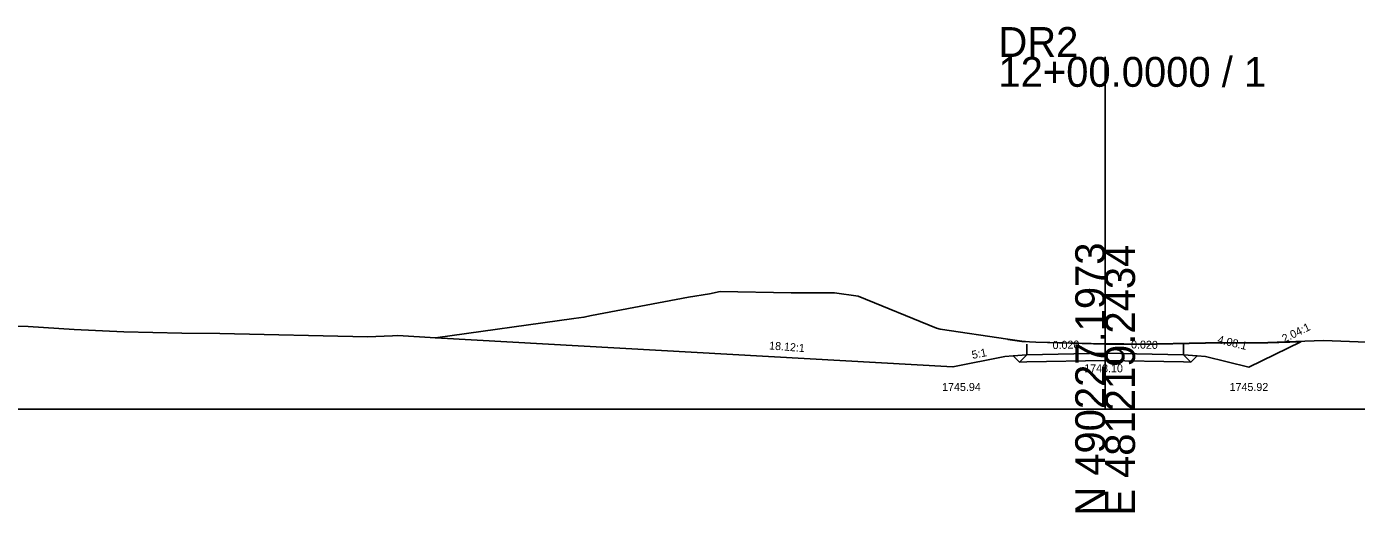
# Model space of a CAD drawing. Extents: x -26 to 403, y -10 to 2576.
# Drawn here: x 98.9 to 223.5, y 1990.3 to 2035.8 of the extents above; entities that cross this region are included whole.
import ezdxf

# ---------------------------------------------------------------- set-up
doc = ezdxf.new("R2010")
doc.units = 0
for name, color, linetype in [('Exist Cross Section Cell', 7, 'Continuous'), ('Exist XS Center Line Elevation Label', 7, 'Continuous'), ('Exist XS Ground Line', 7, 'Continuous'), ('Prop Road Sect_ Boring - Header (ID Tx)', 7, 'Continuous'), ('Prop XS Ditch Slope Text', 7, 'Continuous'), ('Prop XS Ditch Standard Text', 7, 'Continuous'), ('Prop XS Dump Level', 7, 'Continuous'), ('Prop XS Earthwork Shape', 7, 'Continuous'), ('Prop XS EOT Tick Mark', 7, 'Continuous'), ('Prop XS Finish Grade', 7, 'Continuous'), ('Prop XS Finish Grade Earthwork', 7, 'Continuous'), ('Prop XS Finish Grade Pavement', 7, 'Continuous'), ('Prop XS Pvmt Edge Slope', 7, 'Continuous'), ('Prop XS SE Text', 7, 'Continuous'), ('Prop XS Side Slope Text', 7, 'Continuous'), ('Prop XS Subgrade Earthwork', 7, 'Continuous')]:
    doc.layers.add(name, color=color, linetype=linetype)

msp = doc.modelspace()

# ---------------------------------------------------------------- linework, layer by layer
at = {"layer": 'Exist Cross Section Cell'}
for p, q in [((200, 2000), (200, 2033)), ((0, 2000), (200, 2000)), ((200, 2000), (400, 2000))]:
    msp.add_line(p, q, dxfattribs=at)
at = {"layer": 'Exist XS Ground Line'}
msp.add_lwpolyline([(93.86, 2007.76), (99.07, 2007.74), (103.39, 2007.45), (108.05, 2007.23), (113.46, 2007.11), (117.03, 2007.09), (130.87, 2006.78), (133.21, 2006.87), (133.72, 2006.9), (137.24, 2006.67), (150.21, 2008.49), (151.16, 2008.6), (151.88, 2008.75), (160.97, 2010.48), (162.92, 2010.8), (163.93, 2011), (170.58, 2010.89), (174.05, 2010.89), (174.65, 2010.88), (176.86, 2010.57), (184.2, 2007.58), (184.55, 2007.47), (190.88, 2006.55), (192.2, 2006.37), (192.91, 2006.31), (193.51, 2006.28), (200, 2006.1), (201.76, 2006.1), (203.32, 2006.09), (209.39, 2006.2), (215.24, 2006.22), (220.47, 2006.42), (226.16, 2006.2)], dxfattribs=at)
at = {"layer": 'Prop Road Sect_ Boring - Header (ID Tx)'}
for points in [[(192.65, 2005.08), (191.37, 2004.97), (191.96, 2004.4)], [(207.35, 2005.08), (208.63, 2004.97), (208.04, 2004.4)]]:
    msp.add_lwpolyline(points, close=True, dxfattribs=at)
at = {"layer": 'Prop XS Dump Level'}
for p, q in [((192.65, 2005.08), (200, 2005.22)), ((200, 2005.22), (207.35, 2005.08))]:
    msp.add_line(p, q, dxfattribs=at)
at = {"layer": 'Prop XS Earthwork Shape'}
msp.add_lwpolyline([(209.39, 2006.17), (215.24, 2006.19), (218.35, 2006.31), (213.47, 2003.92), (209.39, 2004.92), (208.63, 2004.97), (208.04, 2004.4), (207.35, 2004.41), (200, 2004.55), (192.65, 2004.41), (191.96, 2004.4), (191.37, 2004.97), (190.61, 2004.92), (185.74, 2003.94), (137.24, 2006.67), (150.21, 2008.49), (151.16, 2008.6), (151.88, 2008.75), (160.97, 2010.48), (162.92, 2010.8), (163.93, 2011), (170.58, 2010.89), (174.05, 2010.89), (174.65, 2010.88), (176.86, 2010.57), (184.2, 2007.58), (184.55, 2007.47), (190.88, 2006.55), (190.88, 2006.53), (192.2, 2006.34), (192.91, 2006.29), (193.51, 2006.25), (200, 2006.07), (201.76, 2006.07), (203.32, 2006.06)], close=True, dxfattribs=at)
at = {"layer": 'Prop XS EOT Tick Mark'}
for p, q in [((192.65, 2005.08), (192.65, 2006.08)), ((207.35, 2005.08), (207.35, 2006.08))]:
    msp.add_line(p, q, dxfattribs=at)
at = {"layer": 'Prop XS Finish Grade'}
for p, q in [((192.65, 2005.08), (191.37, 2004.97)), ((207.35, 2005.08), (208.63, 2004.97))]:
    msp.add_line(p, q, dxfattribs=at)
at = {"layer": 'Prop XS Finish Grade Earthwork'}
for p, q in [((185.74, 2003.94), (137.24, 2006.67)), ((213.47, 2003.92), (218.35, 2006.31)), ((190.61, 2004.92), (185.74, 2003.94)), ((191.37, 2004.97), (190.61, 2004.92)), ((208.63, 2004.97), (209.39, 2004.92)), ((209.39, 2004.92), (213.47, 2003.92))]:
    msp.add_line(p, q, dxfattribs=at)
at = {"layer": 'Prop XS Finish Grade Pavement'}
for p, q in [((192.65, 2005.08), (200, 2005.22)), ((200, 2005.22), (207.35, 2005.08))]:
    msp.add_line(p, q, dxfattribs=at)
at = {"layer": 'Prop XS Pvmt Edge Slope'}
for p, q in [((192.65, 2005.08), (191.96, 2004.4)), ((207.35, 2005.08), (208.04, 2004.4))]:
    msp.add_line(p, q, dxfattribs=at)
at = {"layer": 'Prop XS Subgrade Earthwork'}
for p, q in [((191.96, 2004.4), (191.37, 2004.97)), ((192.65, 2004.41), (191.96, 2004.4)), ((200, 2004.55), (192.65, 2004.41)), ((207.35, 2004.41), (200, 2004.55)), ((207.35, 2004.41), (208.04, 2004.4)), ((208.04, 2004.4), (208.63, 2004.97))]:
    msp.add_line(p, q, dxfattribs=at)

# ---------------------------------------------------------------- texts
at = {"layer": 'Exist Cross Section Cell'}
for s, p in [('DR2', (190, 2033)), ('12+00.0000 / 1', (190, 2030.2))]:
    msp.add_text(s, height=2.8, dxfattribs=at).set_placement(p)
for s, p in [('N 490227.1973', (200, 1990)), ('E 481219.2434', (202.8, 1990))]:
    msp.add_text(s, height=2.8, rotation=90, dxfattribs=at).set_placement(p)
at = {"layer": 'Exist XS Center Line Elevation Label'}
msp.add_text('1748.10', height=0.75, dxfattribs=at).set_placement((198.04, 2003.44))
at = {"layer": 'Prop XS Ditch Slope Text'}
for s, rotation, p in [('4.08:1', 346.2259, (210.48, 2006.19)), ('5:1', 11.3099, (187.58, 2004.69))]:
    msp.add_text(s, height=0.75, rotation=rotation, dxfattribs=at).set_placement(p)
at = {"layer": 'Prop XS Ditch Standard Text'}
for s, p in [('1745.94', (184.72, 2001.69)), ('1745.92', (211.66, 2001.69))]:
    msp.add_text(s, height=0.75, dxfattribs=at).set_placement(p)
at = {"layer": 'Prop XS Dump Level'}
for p in [(190.61, 2004.88), (209.39, 2004.88)]:
    msp.add_text('Case1', height=0.04, dxfattribs=at).set_placement(p)
at = {"layer": 'Prop XS SE Text'}
for rotation, p in [(1.1458, (195.08, 2005.62)), (358.8542, (202.42, 2005.68))]:
    msp.add_text('0.020', height=0.75, rotation=rotation, dxfattribs=at).set_placement(p)
at = {"layer": 'Prop XS Side Slope Text'}
for s, rotation, p in [('2.04:1', 26.1183, (216.8, 2006.21)), ('18.12:1', 355.5556, (168.49, 2005.59))]:
    msp.add_text(s, height=0.75, rotation=rotation, dxfattribs=at).set_placement(p)

doc.saveas('drawing.dxf')
